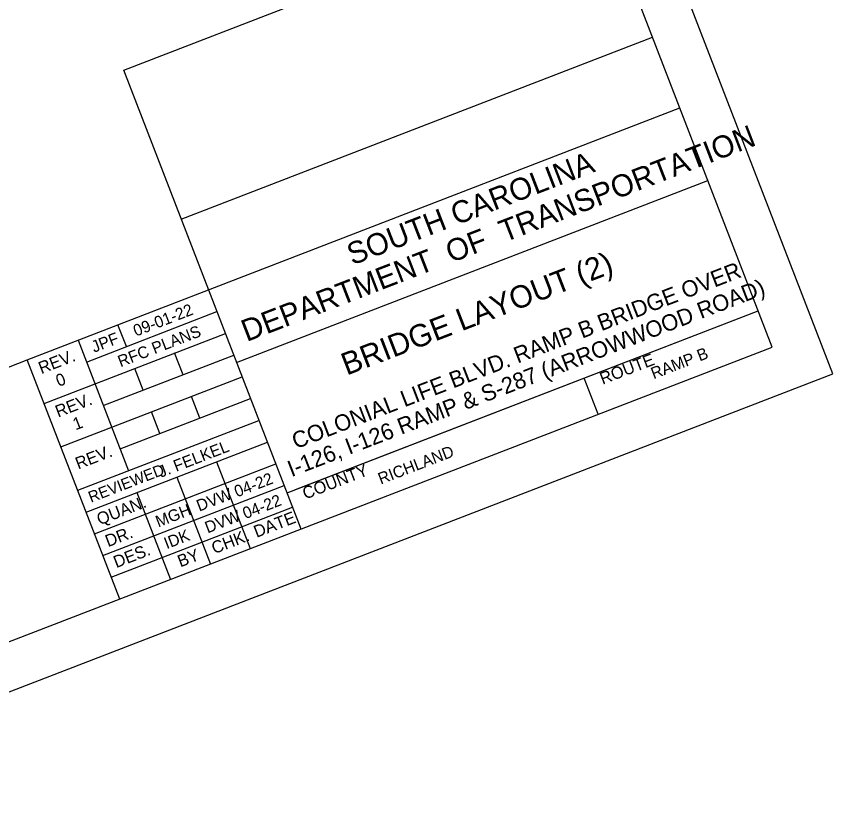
# Model space of a CAD drawing. Extents: x 1971188 to 1971603, y 795903 to 796238.
# Drawn here: x 1971515.3 to 1971602.8, y 795987.3 to 796071.3 of the extents above; entities that cross this region are included whole.
import ezdxf

# ---------------------------------------------------------------- set-up
doc = ezdxf.new("R2010")
doc.units = 0
for name, color, linetype in [('BR_BORDER LINES', 7, 'Continuous'), ('BR_TEXT', 7, 'Continuous'), ('Level 31', 7, 'Continuous')]:
    doc.layers.add(name, color=color, linetype=linetype)

msp = doc.modelspace()

# ---------------------------------------------------------------- linework, layer by layer
at = {"layer": 'BR_BORDER LINES'}
for p, q in [((1971596.323, 796035.824), (1971520.663, 796231.721)), ((1971526.781, 796065.53), (1971577.312, 796085.047)), ((1971532.961, 796049.535), (1971583.49, 796069.051)), ((1971545.792, 796016.308), (1971526.781, 796065.53)), ((1971516.449, 796034.456), (1971586.414, 796061.479)), ((1971538.886, 796034.188), (1971589.419, 796053.705)), ((1971522.791, 796034.226), (1971536.784, 796039.63)), ((1971544.291, 796020.195), (1971594.821, 796039.711)), ((1971545.201, 796020.547), (1971594.821, 796039.711)), ((1971527.067, 796035.877), (1971526.166, 796038.209)), ((1971518.25, 796029.792), (1971537.685, 796037.298)), ((1971521.89, 796036.558), (1971527.295, 796022.565)), ((1971282.272, 795914.531), (1971596.323, 796035.824)), ((1971524.593, 796029.561), (1971538.586, 796034.966)), ((1971533.144, 796032.864), (1971532.243, 796035.196)), ((1971466.4, 796015.126), (1971516.449, 796034.456)), ((1971526.357, 796008.802), (1971516.449, 796034.456)), ((1971538.886, 796034.188), (1971538.886, 796034.188)), ((1971528.868, 796031.213), (1971527.968, 796033.545)), ((1971520.052, 796025.127), (1971539.487, 796032.634)), ((1971577.665, 796028.619), (1971576.164, 796032.506)), ((1971526.394, 796024.897), (1971540.387, 796030.301)), ((1971534.945, 796028.2), (1971534.045, 796030.532)), ((1971530.67, 796026.548), (1971529.769, 796028.881)), ((1971521.853, 796020.463), (1971541.288, 796027.969)), ((1971522.754, 796018.131), (1971542.189, 796025.637)), ((1971523.655, 796015.799), (1971543.09, 796023.305)), ((1971536.747, 796023.535), (1971540.35, 796014.207)), ((1971532.471, 796021.884), (1971536.074, 796012.555)), ((1971524.555, 796013.466), (1971543.99, 796020.973)), ((1971528.196, 796020.233), (1971531.799, 796010.904)), ((1971525.456, 796011.134), (1971544.891, 796018.64))]:
    msp.add_line(p, q, dxfattribs=at)
at = {"layer": 'Level 31'}
msp.add_line((1971565.74, 796039.841), (1971565.74, 796039.841), dxfattribs=at)
msp.add_line((1971565.74, 796039.841), (1971565.74, 796039.841), dxfattribs=at)
msp.add_lwpolyline([(1971266.971, 795903.262), (1971602.794, 796032.965), (1971523.531, 796238.19), (1971187.708, 796108.487)], close=True, dxfattribs=at)

# ---------------------------------------------------------------- texts
at = {"layer": 'BR_TEXT'}
for s, height, p in [('DEPARTMENT  OF  TRANSPORTATION', 2.3587, (1971539.967, 796036.364)), ('SOUTH CAROLINA', 2.3587, (1971551.296, 796044.575)), ('BRIDGE LAYOUT (2)', 2.4, (1971550.689, 796032.756)), ('COLONIAL LIFE BLVD. RAMP B BRIDGE OVER', 1.75, (1971545.237, 796024.866)), ('I-126, I-126 RAMP & S-287 (ARROWWOOD ROAD) ', 1.75, (1971544.763, 796021.869)), ('09-01-22', 1.2499, (1971528.096, 796036.944)), ('RFC PLANS', 1.2499, (1971526.443, 796033.652)), ('JPF', 1.2499, (1971523.606, 796035.21)), ('REV.', 1.3001, (1971517.949, 796032.923)), ('RAMP B', 1.2499, (1971583.598, 796032.371)), ('ROUTE', 1.3001, (1971578.129, 796031.781)), ('0', 1.3, (1971519.807, 796031.55)), ('REV.', 1.3001, (1971519.75, 796028.258)), ('1', 1.3, (1971521.627, 796026.893)), ('REV.', 1.3001, (1971521.903, 796022.684)), ('J. FELKEL', 1.2499, (1971530.758, 796021.805)), ('RICHLAND', 1.2499, (1971554.344, 796021.072)), ('REVIEWED', 1.2, (1971523.273, 796019.119)), ('COUNTY', 1.3001, (1971546.256, 796019.471)), ('04-22', 1.2499, (1971538.926, 796019.699)), ('DVW', 1.2499, (1971534.876, 796018.169)), ('QUAN.', 1.3001, (1971524.198, 796016.707)), ('04-22', 1.2499, (1971539.826, 796017.367)), ('MGH', 1.2499, (1971530.492, 796016.476)), ('DVW', 1.2499, (1971535.777, 796015.837)), ('DATE', 1.3001, (1971541.026, 796015.362)), ('DR.', 1.3001, (1971525.106, 796014.361)), ('IDK', 1.2499, (1971531.393, 796014.144)), ('CHK.', 1.3001, (1971536.5, 796013.613)), ('DES.', 1.3001, (1971525.985, 796012.114)), ('BY', 1.3001, (1971532.859, 796012.192))]:
    msp.add_text(s, height=height, rotation=21.11769, dxfattribs=at).set_placement(p)

doc.saveas('drawing.dxf')
